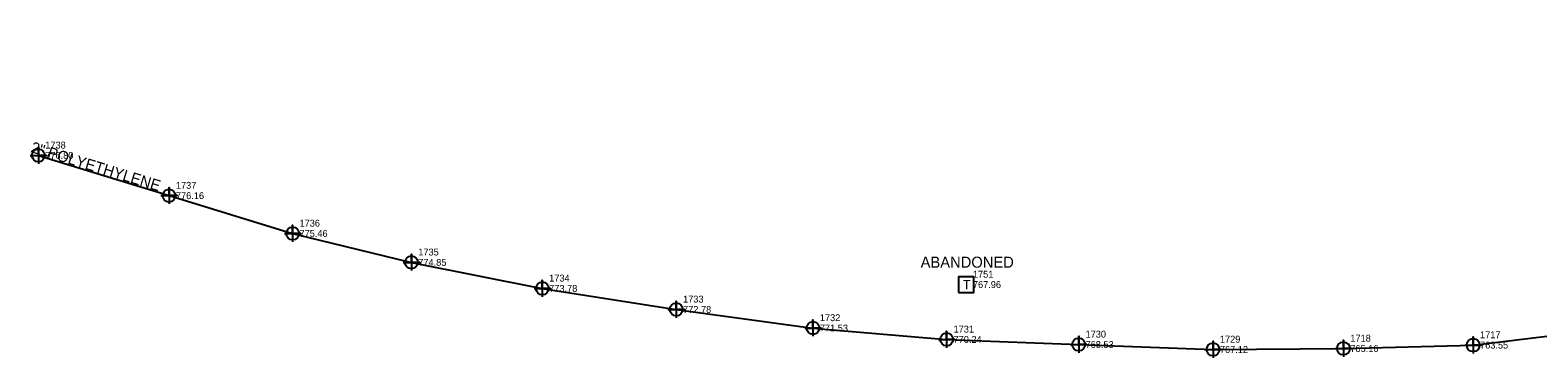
# Model space of a CAD drawing. Extents: x 1622486 to 1624761, y 758733 to 760816.
# Drawn here: x 1622545 to 1623093, y 760136 to 760255 of the extents above; entities that cross this region are included whole.
import ezdxf

# ---------------------------------------------------------------- set-up
doc = ezdxf.new("R2010")
doc.units = 0
for name, color, linetype in [('Exist Structure Minor Pipes CMP 15 Inch Invert', 7, 'Continuous'), ('Exist Structure Minor Pipes RCP 30 Inch Text', 7, 'Continuous'), ('Exist Utilities Gas UG Line SUE', 7, 'Continuous'), ('Exist Utilities Gas UG Line SUE Cogo Elevation', 7, 'Continuous'), ('Exist Utilities Gas UG Line SUE Cogo Number', 7, 'Continuous'), ('Exist Utilities Gas UG Line SUE Cogo Point CELL', 7, 'Continuous'), ('Exist Utilities Telephone Pedestal CELL', 7, 'Continuous'), ('Exist Utilities Telephone Pedestal Cogo Elevation', 7, 'Continuous'), ('Exist Utilities Telephone Pedestal Cogo Number', 7, 'Continuous')]:
    doc.layers.add(name, color=color, linetype=linetype)

msp = doc.modelspace()

# ---------------------------------------------------------------- linework, layer by layer
at = {"layer": 'Exist Utilities Gas UG Line SUE'}
msp.add_lwpolyline([(1622547.81, 760209.85), (1622595.31, 760195.24), (1622640.24, 760181.51), (1622683.43, 760171.03), (1622731.01, 760161.58), (1622779.7, 760153.95), (1622829.42, 760147.2), (1622878.02, 760143.06), (1622926.02, 760141.22), (1622974.86, 760139.4), (1623022.29, 760139.76), (1623069.44, 760141), (1623117.1, 760146.8), (1623164.02, 760152.34), (1623212.66, 760158.91), (1623259.85, 760168.99), (1623303.16, 760183.35), (1623341.71, 760201.94), (1623421.45, 760255.29)], dxfattribs=at)
at = {"layer": 'Exist Utilities Gas UG Line SUE Cogo Point CELL'}
for points in [[(1622544.81, 760209.85), (1622550.81, 760209.85), (1622547.81, 760209.85), (1622547.81, 760212.85), (1622547.81, 760206.85)], [(1622592.31, 760195.24), (1622598.31, 760195.24), (1622595.31, 760195.24), (1622595.31, 760198.24), (1622595.31, 760192.24)], [(1622637.24, 760181.51), (1622643.24, 760181.51), (1622640.24, 760181.51), (1622640.24, 760184.51), (1622640.24, 760178.51)], [(1622680.43, 760171.03), (1622686.43, 760171.03), (1622683.43, 760171.03), (1622683.43, 760174.03), (1622683.43, 760168.03)], [(1622728.01, 760161.58), (1622734.01, 760161.58), (1622731.01, 760161.58), (1622731.01, 760164.58), (1622731.01, 760158.58)], [(1622776.7, 760153.95), (1622782.7, 760153.95), (1622779.7, 760153.95), (1622779.7, 760156.95), (1622779.7, 760150.95)], [(1622826.42, 760147.2), (1622832.42, 760147.2), (1622829.42, 760147.2), (1622829.42, 760150.2), (1622829.42, 760144.2)], [(1622875.02, 760143.06), (1622881.02, 760143.06), (1622878.02, 760143.06), (1622878.02, 760146.06), (1622878.02, 760140.06)], [(1622923.02, 760141.22), (1622929.02, 760141.22), (1622926.02, 760141.22), (1622926.02, 760144.22), (1622926.02, 760138.22)], [(1623019.29, 760139.76), (1623025.29, 760139.76), (1623022.29, 760139.76), (1623022.29, 760142.76), (1623022.29, 760136.76)], [(1623066.44, 760141), (1623072.44, 760141), (1623069.44, 760141), (1623069.44, 760144), (1623069.44, 760138)], [(1622971.86, 760139.4), (1622977.86, 760139.4), (1622974.86, 760139.4), (1622974.86, 760142.4), (1622974.86, 760136.4)]]:
    msp.add_lwpolyline(points, dxfattribs=at)
for centre in [(1622547.81, 760209.85), (1622595.31, 760195.24), (1622640.24, 760181.51), (1622683.43, 760171.03), (1622731.01, 760161.58), (1622779.7, 760153.95), (1622829.42, 760147.2), (1622878.02, 760143.06), (1622926.02, 760141.22), (1623069.44, 760141), (1622974.86, 760139.4), (1623022.29, 760139.76)]:
    msp.add_circle(centre, 2.34, dxfattribs=at)
at = {"layer": 'Exist Utilities Telephone Pedestal CELL'}
msp.add_line((1622885.06, 760162.97), (1622885.06, 760162.97), dxfattribs=at)
msp.add_lwpolyline([(1622882.34, 760160.14), (1622887.93, 760160.14), (1622887.93, 760165.74), (1622882.34, 760165.74), (1622882.34, 760160.14)], dxfattribs=at)

# ---------------------------------------------------------------- texts
at = {"layer": 'Exist Structure Minor Pipes CMP 15 Inch Invert'}
msp.add_text('ABANDONED', height=4, dxfattribs=at).set_placement((1622868.56, 760169.1))
at = {"layer": 'Exist Structure Minor Pipes RCP 30 Inch Text'}
msp.add_text('2" POLYETHYLENE', height=4, rotation=343.0065, dxfattribs=at).set_placement((1622544.76, 760211.08))
at = {"layer": 'Exist Utilities Gas UG Line SUE Cogo Elevation'}
for s, p in [('776.80', (1622550.31, 760208.6)), ('776.16', (1622597.81, 760193.99)), ('775.46', (1622642.74, 760180.26)), ('774.85', (1622685.93, 760169.78)), ('773.78', (1622733.51, 760160.33)), ('772.78', (1622782.2, 760152.7)), ('771.53', (1622831.92, 760145.95)), ('770.24', (1622880.52, 760141.81)), ('768.53', (1622928.52, 760139.97)), ('767.12', (1622977.36, 760138.15)), ('765.16', (1623024.79, 760138.51)), ('763.55', (1623071.94, 760139.75))]:
    msp.add_text(s, height=2.5, dxfattribs=at).set_placement(p)
at = {"layer": 'Exist Utilities Gas UG Line SUE Cogo Number'}
for s, p in [('1738', (1622550.31, 760212.35)), ('1737', (1622597.81, 760197.74)), ('1736', (1622642.74, 760184.01)), ('1735', (1622685.93, 760173.53)), ('1734', (1622733.51, 760164.08)), ('1733', (1622782.2, 760156.45)), ('1732', (1622831.92, 760149.7)), ('1731', (1622880.52, 760145.56)), ('1730', (1622928.52, 760143.72)), ('1729', (1622977.36, 760141.9)), ('1718', (1623024.79, 760142.26)), ('1717', (1623071.94, 760143.5))]:
    msp.add_text(s, height=2.5, dxfattribs=at).set_placement(p)
at = {"layer": 'Exist Utilities Telephone Pedestal CELL'}
msp.add_text('T', height=3.42, dxfattribs=at).set_placement((1622883.93, 760161.26))
at = {"layer": 'Exist Utilities Telephone Pedestal Cogo Elevation'}
msp.add_text('767.96', height=2.5, dxfattribs=at).set_placement((1622887.56, 760161.72))
at = {"layer": 'Exist Utilities Telephone Pedestal Cogo Number'}
msp.add_text('1751', height=2.5, dxfattribs=at).set_placement((1622887.56, 760165.47))

doc.saveas('drawing.dxf')
